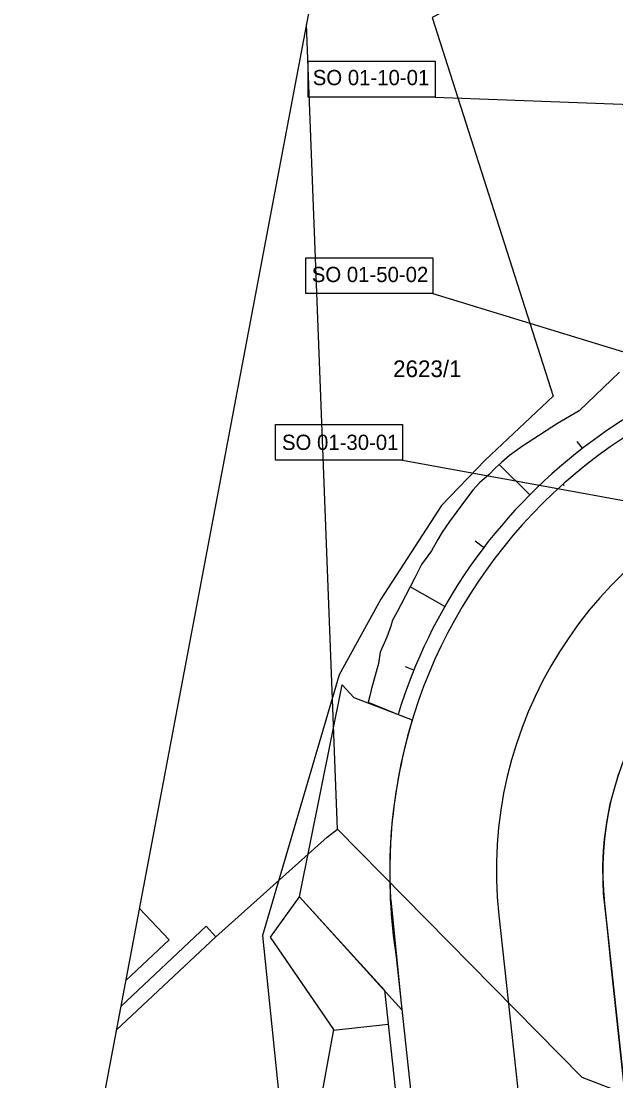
# Model space of a CAD drawing. Extents: x -526979 to -525529, y -1078878 to -1076692.
# Drawn here: x -526862.1 to -526784, y -1078144.8 to -1078005.6 of the extents above; entities that cross this region are included whole.
import ezdxf

# ---------------------------------------------------------------- set-up
doc = ezdxf.new("R2010")
doc.units = 0
for name, color, linetype in [('DZ_DO_ostatní', 7, 'Continuous'), ('Hranice parcel', 7, 'Continuous'), ('Parcelní čísla', 7, 'Continuous'), ('Vnitřní kresba', 7, 'Continuous'), ('Vrstva 10', 7, 'Continuous'), ('Vrstva 12', 7, 'Continuous'), ('Vrstva 63', 7, 'Continuous')]:
    doc.layers.add(name, color=color, linetype=linetype)

msp = doc.modelspace()

# ---------------------------------------------------------------- linework, layer by layer
at = {"layer": 'DZ_DO_ostatní'}
msp.add_lwpolyline([(-526801.98, -1078001.87), (-526808.1, -1078005.12), (-526792.19, -1078054.85), (-526801.15, -1078063.29), (-526806.87, -1078069.25), (-526814.87, -1078081.55), (-526820.35, -1078091.47), (-526830.39, -1078125.71), (-526826.9, -1078159.87), (-526822.68, -1078170.08), (-526800.04, -1078148.77), (-526787.28, -1078164.73), (-526779.79, -1078159.57), (-526760, -1078145.97), (-526740.32, -1078124.33), (-526771.8, -1078020.17), (-526780.94, -1078005.85)], dxfattribs=at)
at = {"layer": 'Hranice parcel'}
msp.add_lwpolyline([(-526846.6, -1078122.15), (-526842.68, -1078126.29), (-526848.39, -1078131.63)], dxfattribs=at)
at = {"layer": 'Vnitřní kresba'}
for p, q in [((-526820.56, -1078111.77), (-526824.64, -1078006.05)), ((-526836.56, -1078125.89), (-526821.92, -1078112.81)), ((-526821.92, -1078112.81), (-526820.56, -1078111.77)), ((-526820.56, -1078111.77), (-526788.44, -1078144.33)), ((-526837.8, -1078124.49), (-526849.04, -1078135.05)), ((-526836.56, -1078125.89), (-526837.8, -1078124.49)), ((-526849.63, -1078138.15), (-526836.56, -1078125.89)), ((-526788.44, -1078144.33), (-526775.16, -1078149.49))]:
    msp.add_line(p, q, dxfattribs=at)
at = {"layer": 'Vrstva 10'}
for p, q in [((-526788.34, -1078061.71), (-526789.03, -1078060.82)), ((-526788.34, -1078061.71), (-526789.03, -1078060.82)), ((-526795.28, -1078067.83), (-526799.28, -1078063.85)), ((-526795.28, -1078067.83), (-526799.28, -1078063.85)), ((-526790.87, -1078066.4), (-526790.81, -1078066.59)), ((-526790.87, -1078066.4), (-526790.81, -1078066.59)), ((-526801.34, -1078074.77), (-526802.47, -1078073.92)), ((-526801.34, -1078074.77), (-526802.47, -1078073.92)), ((-526806.46, -1078082.5), (-526811.01, -1078079.9)), ((-526806.46, -1078082.5), (-526811.01, -1078079.9)), ((-526810.53, -1078090.86), (-526811.62, -1078090.42)), ((-526810.53, -1078090.86), (-526811.62, -1078090.42)), ((-526813.56, -1078121.03), (-526812.08, -1078135.48)), ((-526813.56, -1078121.03), (-526812.08, -1078135.48)), ((-526785.45, -1078121.53), (-526780.45, -1078167.87)), ((-526785.45, -1078121.53), (-526780.45, -1078167.87)), ((-526799.35, -1078123.04), (-526793.02, -1078181.36)), ((-526799.35, -1078123.04), (-526793.02, -1078181.36)), ((-526812.84, -1078128.52), (-526808.24, -1078170.87)), ((-526812.84, -1078128.52), (-526808.24, -1078170.87)), ((-526813.88, -1078137.43), (-526821.06, -1078138.21)), ((-526813.88, -1078137.43), (-526821.06, -1078138.21))]:
    msp.add_line(p, q, dxfattribs=at)
for points in [[(-526783.47, -1078051.7), (-526788.77, -1078056.79), (-526791.65, -1078058.47), (-526796.22, -1078061.44), (-526797.93, -1078062.67), (-526798.99, -1078063.59), (-526799.77, -1078064.28), (-526800.6, -1078065.15), (-526801.89, -1078066.25), (-526802.75, -1078067.23), (-526803.34, -1078067.97), (-526805.85, -1078071.35), (-526806.8, -1078072.74), (-526807.36, -1078073.72), (-526808.19, -1078075.18), (-526809.52, -1078076.98), (-526810.37, -1078078.74), (-526811.01, -1078079.9), (-526812.19, -1078082.2), (-526812.7, -1078083.19), (-526813.36, -1078084.4), (-526813.49, -1078084.97), (-526814.06, -1078086.54), (-526814.93, -1078088.51), (-526815.16, -1078089.98), (-526816.12, -1078093.45), (-526816.32, -1078094.26), (-526816.51, -1078095.06), (-526812.59, -1078096.68)], [(-526783.47, -1078051.7), (-526788.77, -1078056.79), (-526791.65, -1078058.47), (-526796.22, -1078061.44), (-526797.93, -1078062.67), (-526798.99, -1078063.59), (-526799.77, -1078064.28), (-526800.6, -1078065.15), (-526801.89, -1078066.25), (-526802.75, -1078067.23), (-526803.34, -1078067.97), (-526805.85, -1078071.35), (-526806.8, -1078072.74), (-526807.36, -1078073.72), (-526808.19, -1078075.18), (-526809.52, -1078076.98), (-526810.37, -1078078.74), (-526811.01, -1078079.9), (-526812.19, -1078082.2), (-526812.7, -1078083.19), (-526813.36, -1078084.4), (-526813.49, -1078084.97), (-526814.06, -1078086.54), (-526814.93, -1078088.51), (-526815.16, -1078089.98), (-526816.12, -1078093.45), (-526816.32, -1078094.26), (-526816.51, -1078095.06), (-526812.59, -1078096.68)], [(-526812.08, -1078135.48), (-526825.55, -1078120.63), (-526819.93, -1078092.78), (-526818.42, -1078094.46), (-526810.72, -1078097.4)], [(-526812.08, -1078135.48), (-526825.55, -1078120.63), (-526819.93, -1078092.78), (-526818.42, -1078094.46), (-526810.72, -1078097.4)], [(-526780.45, -1078167.85), (-526784.61, -1078129.28), (-526785.04, -1078125.3), (-526785.38, -1078122.12), (-526785.57, -1078120.2), (-526785.65, -1078118.72), (-526785.67, -1078116.49), (-526785.59, -1078114.57), (-526785.46, -1078113.09), (-526785.17, -1078110.89), (-526784.7, -1078108.42), (-526783.58, -1078104.43)], [(-526780.45, -1078167.85), (-526784.61, -1078129.28), (-526785.04, -1078125.3), (-526785.38, -1078122.12), (-526785.57, -1078120.2), (-526785.65, -1078118.72), (-526785.67, -1078116.49), (-526785.59, -1078114.57), (-526785.46, -1078113.09), (-526785.17, -1078110.89), (-526784.7, -1078108.42), (-526783.58, -1078104.43)], [(-526811.52, -1078159.16), (-526822.06, -1078169.36), (-526825.17, -1078160.64), (-526821.03, -1078138.06), (-526829.36, -1078125.93), (-526825.55, -1078120.63), (-526814.38, -1078132.91), (-526811.52, -1078159.16)], [(-526811.52, -1078159.16), (-526822.06, -1078169.36), (-526825.17, -1078160.64), (-526821.03, -1078138.06), (-526829.36, -1078125.93), (-526825.55, -1078120.63), (-526814.38, -1078132.91), (-526811.52, -1078159.16)]]:
    msp.add_lwpolyline(points, dxfattribs=at)
for centre, radius, start, end in [((-526745.68, -1078117.21), 70, 111.9172, 127.4094), ((-526745.68, -1078117.21), 70, 111.9172, 127.4094), ((-526745.67, -1078117.21), 68, 111.9213, 164.1237), ((-526745.67, -1078117.21), 68, 111.9213, 164.1237), ((-526745.67, -1078117.21), 70, 127.4141, 162.9502), ((-526745.67, -1078117.21), 70, 127.4141, 162.9502), ((-526745.67, -1078117.2), 54, 109.4821, 186.2031), ((-526745.67, -1078117.2), 54, 109.4821, 186.2031), ((-526745.66, -1078117.22), 40.02, 109.4913, 186.1744), ((-526745.66, -1078117.22), 40.02, 109.4913, 186.1744), ((-526745.66, -1078117.21), 68.01, 163.0658, 183.2225), ((-526745.66, -1078117.21), 68.01, 163.0658, 183.2225), ((-526743.13, -1078117.62), 70.56, 164.366, 188.8874), ((-526743.13, -1078117.62), 70.56, 164.366, 188.8874)]:
    msp.add_arc(centre, radius, start, end, dxfattribs=at)
at = {"layer": 'Vrstva 12'}
for p, q in [((-526807.71, -1078015.57), (-526753.43, -1078017.63)), ((-526808, -1078041.38), (-526774.89, -1078051.51)), ((-526812.02, -1078063.29), (-526729.57, -1078078.35))]:
    msp.add_line(p, q, dxfattribs=at)
for points in [[(-526824.4, -1078010.87), (-526807.71, -1078010.87), (-526807.71, -1078015.57), (-526824.4, -1078015.57)], [(-526824.69, -1078036.68), (-526808, -1078036.68), (-526808, -1078041.38), (-526824.69, -1078041.38)], [(-526828.71, -1078058.59), (-526812.02, -1078058.59), (-526812.02, -1078063.29), (-526828.71, -1078063.29)]]:
    msp.add_lwpolyline(points, close=True, dxfattribs=at)
at = {"layer": 'Vrstva 63'}
msp.add_line((-526823.09, -1077997.87), (-526862.12, -1078204.21), dxfattribs=at)

# ---------------------------------------------------------------- texts
at = {"layer": 'Parcelní čísla'}
msp.add_text('2623/1', height=2.2, dxfattribs=at).set_placement((-526813.24, -1078052.37))
at = {"layer": 'Vrstva 12'}
for s, p in [('SO 01-10-01', (-526823.8, -1078014.01)), ('SO 01-50-02', (-526823.93, -1078039.88)), ('SO 01-30-01', (-526827.85, -1078061.93))]:
    msp.add_text(s, height=2, dxfattribs=at).set_placement(p)

doc.saveas('drawing.dxf')
